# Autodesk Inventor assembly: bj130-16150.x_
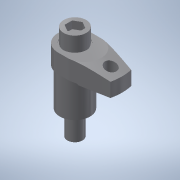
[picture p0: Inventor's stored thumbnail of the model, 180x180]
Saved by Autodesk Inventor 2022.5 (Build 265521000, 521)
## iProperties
Part Number: bj130-16150.x_
Material: 一般
Document SubType Name: Assembly
Designer: ImaoCorp
Sending System: SOLIDWORKS 2017-2017317
MC: AMD64
MC_MODEL: Intel64 Family 6 Model 60 Stepping 3, GenuineIntel
OS: Windows_NT
FRU: Parasolid Version 29.0, build 201,  4-17-2017
FORMAT: text
GUISE: transmit
KEY: bj130-16150
FILE: bj130-16150.x_t
DATE: Fri Mar 15 10:29:43 2019
Author: ImaoCorp
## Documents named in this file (3)
- X:\14_SW2022-Inv2022\00_全2023-1023新製品(TCC)まで\b\bj130-16150\BJ130-16150.iam
- X:\14_SW2022-Inv2022\00_全2023-1023新製品(TCC)まで\b\bj130-16150\bj130-16150_01.ipt
- X:\14_SW2022-Inv2022\00_全2023-1023新製品(TCC)まで\b\bj130-16150\bj130-16150_02.ipt
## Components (2 placed, 2 different names)
1. bj130-16150_01
2. bj130-16150_02
